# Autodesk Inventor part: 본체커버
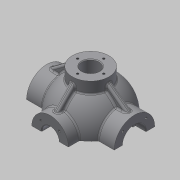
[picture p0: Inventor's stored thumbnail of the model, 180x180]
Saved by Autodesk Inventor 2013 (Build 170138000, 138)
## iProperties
Created: 2015-12
Part Number: 본체커버
Material: 일반
Document SubType Name: Modeling
Designer: mduedu
Density: 1 g/cm^3
Mass: 217.614 g
Surface Area: 460.056 cm^2
Volume: 217.614 cm^3
Author: mduedu
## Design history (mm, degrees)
sketch "스케치1"
  geometry: L1 (-53, 0)-(53, 0); A1 r 53 centre (0, 0) between (53, 0) and (-53, 0); 2 further points
  constraints: 2 coincident, 2 end point, 2 point on circle, 1 centre point, 1 horizontal, 1 midpoint
  dimensions: "d0" = 53 radius of A1
revolve "회전1" sketch "스케치1" stored, may be unused: angle "d2" = 90 deg
feature "쉘1" dims "d11" = 10
node "작업 평면1"
sketch "스케치2"
  geometry: C1 r 31 at (0, 0); 1 further point
  constraints: 1 centre point, 1 coincident
  dimensions: "d4" = 62 diameter of C1
extrude "돌출1" join sketch "스케치2" stored distance "d5" = 10; taper "d6" = 0 deg
node "작업 평면2"
sketch "스케치3"
  geometry: C1 r 28 at (0, 0); 1 further point
  constraints: 1 centre point, 1 coincident
  dimensions: "d8" = 56 diameter of C1
extrude "돌출2" join sketch "스케치3" stored distance "d9" = 10; taper "d10" = 0 deg
hole "구멍1" diameter "d14" = 35; stored, may be unused: countersink angle "d18" = 90 deg, drill point angle "d20" = 0 deg; dims "d12" = 10, "d13" = 10, "d15" = 6, "d16" = 4, "d17" = 2, "d19" = 16
hole "구멍2" diameter "d23" = 27; stored, may be unused: countersink angle "d27" = 90 deg, drill point angle "d29" = 0 deg; dims "d21" = 10, "d22" = 10, "d24" = 6, "d25" = 4, "d26" = 2, "d28" = 16
fillet "모깎기1" dims "d30" = 0.3
hole "구멍3" diameter "d33" = 26; stored, may be unused: countersink angle "d37" = 90 deg, drill point angle "d39" = 0 deg; dims "d31" = 10, "d32" = 10, "d34" = 6, "d35" = 4, "d36" = 2, "d38" = 16
chamfer "모따기1" distance "d40" = 1; stored, may be unused: second distance "d41" = 2, angle "d42" = 45 deg
sketch "스케치4"
  geometry: L1 (0, 0)-(0, -25); L2 (0, 0)-(-17.678, -17.678); A1 r 25 centre (0, 0) between (-17.678, -17.678) and (0, -25); 1 further point
  constraints: 4 end point, 2 point on circle, 1 centre point, 1 coincident, 1 vertical
  dimensions: "d43" = 50 diameter of A1; "d47" = 45 deg angle of L1 L2
hole "구멍4" sketch "스케치4" at (-17.678, -17.678) diameter "d49" = 3.242; stored, may be unused: countersink angle "d53" = 90 deg, drill point angle "d55" = 118 deg; dims "d50" = 11, "d51" = 4, "d52" = 2, "d54" = 13
sketch "스케치5"
  geometry: L1 (0, 0)-(0, -20); L2 (0, 0)-(-14.142, -14.142); A1 r 20 centre (0, 0) between (0, -20) and (-14.142, -14.142); 2 further points
  constraints: 4 end point, 2 coincident, 2 point on circle, 1 centre point, 1 vertical
  dimensions: "d59" = 40 diameter of A1; "d65" = 45 deg angle of L1 L2
hole "구멍5" sketch "스케치5" at (-14.142, -14.142) diameter "d67" = 3.242; stored, may be unused: countersink angle "d71" = 90 deg, drill point angle "d73" = 118 deg; dims "d68" = 8, "d69" = 4, "d70" = 2, "d72" = 10
node "작업 평면3"
sketch "스케치6"
  geometry: C1 r 65 at (0, 0); 1 further point
  constraints: 1 centre point, 1 coincident
  dimensions: "d78" = 130 diameter of C1
extrude "돌출3" join sketch "스케치6" distance "d80" = 10; taper "d81" = 0 deg
sketch "스케치7"
  geometry: C1 r 20 at (0, 0); 1 further point
  constraints: 1 centre point, 1 coincident
  dimensions: "d82" = 40 diameter of C1
extrude "돌출4" join sketch "스케치7" stored distance "d84" = 10; taper "d85" = 0 deg
sketch "스케치8"
  geometry: 2 further points
  constraints: 1 coincident
hole "구멍6" sketch "스케치8" at (0, 0) diameter "d86" = 20; stored, may be unused: countersink angle "d90" = 90 deg, drill point angle "d92" = 118 deg; dims "d87" = 7, "d88" = 40, "d89" = 5, "d91" = 10
fillet "모깎기2" dims "d93" = 0.3
sketch "스케치9"
  geometry: L1 (65, -75)-(-65, -75) reference; L2 (-45, -75)-(-38.245, -36.692); A1 r 53 centre (0, 0) between (42.988, 31) and (42.988, -31) reference; 1 further point
  constraints: 2 end point, 1 point on circle, 1 point on line
  dimensions: "d94" = 45 horizontal distance of L2.start point (0, 0); "d95" = 80 deg angle of L2 L1
feature "리브1" sketch "스케치9" dims "d96" = 1, "d97" = 8, "d98" = 0, "d99" = 0, "d100" = 1, "d101" = 1
sketch "스케치10"
  geometry: L1 (0, 0)-(0, -55); L2 (0, 0)-(-38.891, -38.891); A1 r 55 centre (0, 0) between (0, -55) and (-38.891, -38.891); 2 further points
  constraints: 4 end point, 2 coincident, 2 point on circle, 1 centre point, 1 vertical
  dimensions: "d105" = 110 diameter of A1; "d107" = 45 deg angle of L1 L2
hole "구멍7" sketch "스케치10" at (-38.891, -38.891) diameter "d109" = 10; stored, may be unused: countersink angle "d113" = 90 deg, drill point angle "d115" = 118 deg; dims "d110" = 7, "d111" = 40, "d112" = 5, "d114" = 10
fillet "모깎기3" dims "d120" = 3
fillet "모깎기4" dims "d121" = 3, "d122" = 3
fillet "모깎기5" dims "d123" = 3
fillet "모깎기6" dims "d124" = 3
sketch "스케치11"
  geometry: C1 r 5 at (-38.891, 38.891) reference; C2 r 5 at (38.891, 38.891) reference; C3 r 5 at (38.891, -38.891) reference; C4 r 5 at (-38.891, -38.891) reference; C5 r 20 at (0, 0) reference; C6 r 65 at (0, 0) reference; 1 further point
  constraints: 3 other
feature "엠보싱1" sketch "스케치11" dims "d125" = 0.5, "d126" = 0
sketch "스케치12"
  geometry: L1 (0, 100)-(0, -100); L2 (0, 100)-(-150, 100); L3 (-150, 100)-(-150, -100); L4 (-150, -100)-(0, -100); 2 further points
  constraints: 8 end point, 3 perpendicular, 1 coincident, 1 midpoint, 1 vertical
  dimensions: "d127" = 200 distance of L2.end L3.end; "d129" = 150 distance of L3.end L1.end
extrude "돌출5" cut sketch "스케치12" stored distance "d130" = 10; taper "d131" = 0 deg
sketch "스케치13"
  geometry: C1 r 7 at (0, -53); A1 r 53 centre (0, 0) between (-42.113, -32.179) and (42.113, -32.179) reference; 1 further point
  constraints: 1 centre point, 1 point on circle
  dimensions: "d132" = 14 diameter of C1
extrude "돌출6" join sketch "스케치13" distance "d133" = 5; taper "d134" = 0 deg
sketch "스케치14"
  geometry: C1 r 7 at (0, 0) reference; 1 further point
extrude "돌출7" cut sketch "스케치14" stored distance "d135" = 5; taper "d136" = 0 deg
sketch "스케치15"
  geometry: C1 r 2.25 at (0, 53); A1 r 7 centre (0, 53) between (6.965, 52.302) and (-6.965, 52.302) reference; 1 further point
  constraints: 1 centre point, 1 coincident
  dimensions: "d139" = 4.5 diameter of C1
extrude "돌출8" cut sketch "스케치15" stored distance "d141" = 5; taper "d142" = 0 deg
fillet "모깎기7" dims "d143" = 3
fillet "모깎기8" dims "d144" = 1
fillet "모깎기9" dims "d145" = 1
fillet "모깎기10" dims "d146" = 1
node "작업 평면4"
sketch "스케치16"
  geometry: C1 r 28 at (0, 0); 1 further point
  constraints: 1 centre point, 1 coincident
  dimensions: "d148" = 56 diameter of C1
extrude "돌출9" join sketch "스케치16" stored distance "d150" = 5; taper "d151" = 0 deg
hole "구멍8" diameter "d154" = 26; stored, may be unused: countersink angle "d158" = 90 deg, drill point angle "d160" = 118 deg; dims "d152" = 10, "d153" = 10, "d155" = 6, "d156" = 4, "d157" = 2, "d159" = 8
sketch "스케치17" dims "d161" = 40
  geometry: 3 further points
  constraints: 2 vertical alignment, 1 coincident, 2 other
hole "구멍9" sketch "스케치17" at (0, 20) diameter "d163" = 3.242; stored, may be unused: countersink angle "d167" = 90 deg, drill point angle "d169" = 118 deg; dims "d164" = 8, "d165" = 4, "d166" = 2, "d168" = 10
fillet "모깎기11" dims "d173" = 3
chamfer "모따기2" distance "d174" = 1; stored, may be unused: second distance "d175" = 2, angle "d176" = 45 deg
sketch "스케치18"
  geometry: L1 (28, 62)-(28, 46.637) reference; L2 (67, 31)-(44.497, 31) reference; L3 (28, 55)-(60, 31); L4 (-28, 62)-(28, 62) reference; L5 (67, 31)-(67, 0) reference; 1 further point
  constraints: 2 end point, 2 point on line
  dimensions: "d177" = 7 distance from line of L3.start L4; "d178" = 7 distance from line of L3.end L5
feature "리브2" sketch "스케치18" dims "d179" = 1, "d180" = 8, "d181" = 0, "d182" = 0, "d183" = 1, "d184" = 1
fillet "모깎기12" dims "d185" = 3
fillet "모깎기13" dims "d186" = 3
sketch "스케치19"
  geometry: L1 (62, 28)-(46.637, 28) reference; L2 (28, 62)-(28, 46.637) reference; L3 (55, 28)-(28, 55); L4 (0, 62)-(28, 62) reference; L5 (62, 28)-(62, -28) reference; 1 further point
  constraints: 2 end point, 2 point on line
  dimensions: "d187" = 7 distance from line of L3.end L4; "d188" = 7 distance from line of L3.start L5
feature "리브3" sketch "스케치19" dims "d189" = 1, "d190" = 8, "d191" = 0, "d192" = 0, "d193" = 1, "d194" = 1
fillet "모깎기14" dims "d195" = 3
fillet "모깎기15" dims "d196" = 3
node "솔리드1"
mirror "대칭1"
mirror "대칭2"
pattern_circular "원형 패턴1" dims angle "d57" = 360 deg
mirror "대칭3"
pattern_circular "원형 패턴2" dims angle "d75" = 360 deg
pattern_circular "원형 패턴3" dims angle "d103" = 360 deg
pattern_circular "원형 패턴4" dims angle "d118" = 360 deg
pattern_circular "원형 패턴5" dims angle "d171" = 360 deg
mirror "대칭4"
node "투영된 루프1"
other parameters: "d3" = 67, "d7" = 62, "d77" = -85, "d147" = 62
